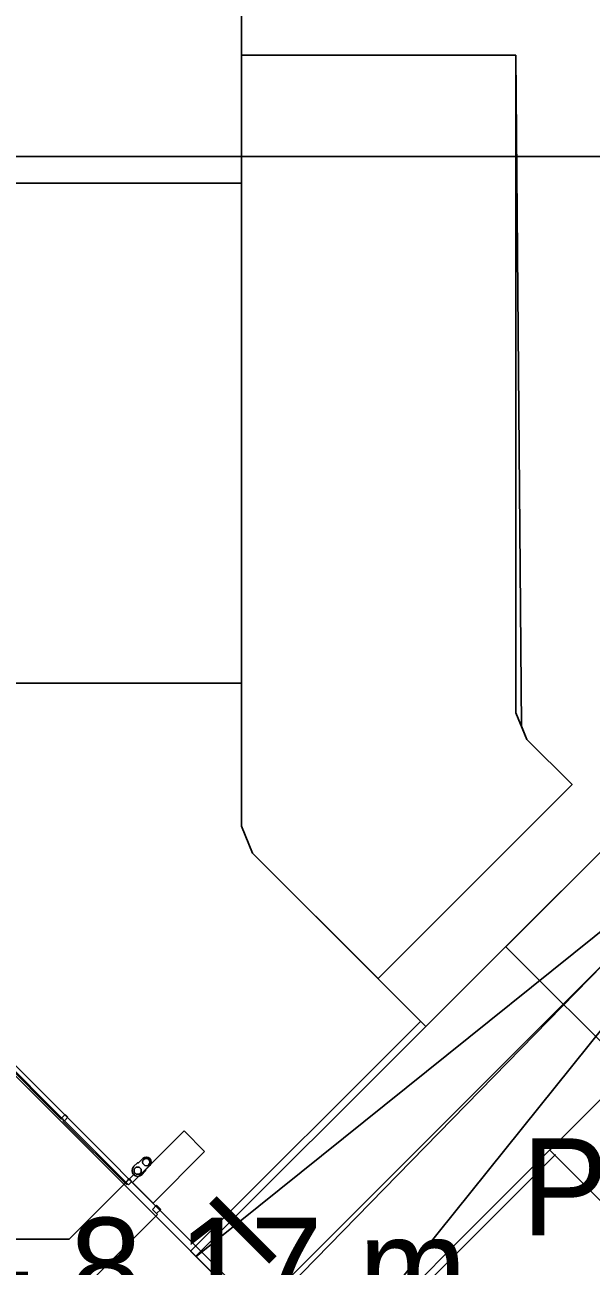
# Model space of a CAD drawing. Extents: x -264234 to -263604, y -1242346 to -1242049.
# Drawn here: x -263906.8 to -263895.14, y -1242233.35 to -1242207.77 of the extents above; entities that cross this region are included whole.
import ezdxf

# ---------------------------------------------------------------- set-up
doc = ezdxf.new("R2010")
doc.units = 0
for name, color, linetype in [('KFA_DAZDOVA_KANALIZACIA_retencna_nadrz_popis', 7, 'Continuous'), ('KFA_DAZDOVA_KANALIZACIA_vetva_I', 7, 'Continuous'), ('KFA_DAZDOVA_KANALIZACIA_vetva_I_popis', 7, 'Continuous'), ('KFA_SITUACIA_DSP', 7, 'Continuous')]:
    doc.layers.add(name, color=color, linetype=linetype)

msp = doc.modelspace()

# ---------------------------------------------------------------- linework, layer by layer
at = {"layer": 'KFA_DAZDOVA_KANALIZACIA_vetva_I'}
msp.add_lwpolyline([(-263814.907, -1242107.856), (-263815.198, -1242164.443), (-263815.189, -1242220.791), (-263852.152, -1242220.736), (-263888.701, -1242220.786), (-263906.731, -1242239.259)], dxfattribs=at)
at = {"layer": 'KFA_SITUACIA_DSP'}
for p, q in [((-263902.343, -1242208.394), (-263902.343, -1242224.282)), ((-263896.693, -1242208.394), (-263902.343, -1242208.394)), ((-263896.578, -1242222.219), (-263896.693, -1242208.394)), ((-263903.343, -1242211.032), (-263921.351, -1242211.032)), ((-263902.343, -1242211.032), (-263903.343, -1242211.032)), ((-263889.023, -1242221.253), (-263906.365, -1242238.596)), ((-263923.393, -1242221.332), (-263903.343, -1242221.332)), ((-263902.343, -1242221.332), (-263903.343, -1242221.332)), ((-263896.463, -1242222.496), (-263896.578, -1242222.219)), ((-263895.535, -1242223.424), (-263896.463, -1242222.496)), ((-263899.53, -1242227.419), (-263895.535, -1242223.424)), ((-263902.343, -1242224.282), (-263902.113, -1242224.837)), ((-263902.113, -1242224.837), (-263899.53, -1242227.419)), ((-263908.663, -1242227.55), (-263895.135, -1242241.078)), ((-263906.055, -1242230.32), (-263907.363, -1242229.012)), ((-263907.345, -1242228.994), (-263906.037, -1242230.303)), ((-263906.046, -1242230.294), (-263905.975, -1242230.223)), ((-263905.975, -1242230.223), (-263905.918, -1242230.28)), ((-263906.037, -1242230.303), (-263906.055, -1242230.32)), ((-263906.017, -1242230.322), (-263906.046, -1242230.294)), ((-263906.019, -1242230.356), (-263906.001, -1242230.338)), ((-263904.711, -1242231.664), (-263906.019, -1242230.356)), ((-263905.989, -1242230.351), (-263906.017, -1242230.322)), ((-263906.001, -1242230.338), (-263904.693, -1242231.647)), ((-263905.918, -1242230.28), (-263905.989, -1242230.351)), ((-263903.526, -1242230.561), (-263904.586, -1242231.622)), ((-263903.101, -1242230.985), (-263903.526, -1242230.561)), ((-263904.162, -1242232.046), (-263903.101, -1242230.985)), ((-263904.484, -1242231.218), (-263904.563, -1242231.296)), ((-263904.465, -1242231.218), (-263904.484, -1242231.218)), ((-263904.376, -1242231.13), (-263904.465, -1242231.218)), ((-263904.533, -1242231.432), (-263905.894, -1242232.793)), ((-263904.397, -1242231.462), (-263904.319, -1242231.383)), ((-263904.319, -1242231.383), (-263904.397, -1242231.462)), ((-263904.231, -1242231.275), (-263904.319, -1242231.364)), ((-263904.319, -1242231.364), (-263904.319, -1242231.383)), ((-263904.726, -1242231.613), (-263904.656, -1242231.543)), ((-263904.698, -1242231.642), (-263904.726, -1242231.613)), ((-263904.693, -1242231.647), (-263904.711, -1242231.664)), ((-263904.67, -1242231.67), (-263904.698, -1242231.642)), ((-263904.599, -1242231.599), (-263904.67, -1242231.67)), ((-263904.656, -1242231.543), (-263904.599, -1242231.599)), ((-263904.586, -1242231.622), (-263904.162, -1242232.046)), ((-263904.091, -1242232.093), (-263904.176, -1242232.178)), ((-263904.176, -1242232.178), (-263904.091, -1242232.263)), ((-263904.006, -1242232.178), (-263904.091, -1242232.093)), ((-263904.091, -1242232.263), (-263904.006, -1242232.178)), ((-263904.091, -1242232.263), (-263904.074, -1242232.281)), ((-263904.074, -1242232.281), (-263906.177, -1242234.384)), ((-263905.894, -1242232.793), (-263918.643, -1242232.793))]:
    msp.add_line(p, q, dxfattribs=at)
for points in [[(-263794.893, -1242227.382), (-263808.968, -1242241.457), (-263894.968, -1242241.457), (-263909.043, -1242227.382), (-263909.043, -1242196.333), (-263914.143, -1242196.333), (-263914.143, -1242132.433), (-263909.043, -1242132.433), (-263909.043, -1242101.382), (-263894.968, -1242087.307), (-263808.968, -1242087.307), (-263794.893, -1242101.382), (-263794.893, -1242227.382)], [(-263811.918, -1242108.434), (-263811.918, -1242220.33), (-263812.262, -1242220.675), (-263809.862, -1242221.669), (-263810.999, -1242222.806), (-263807.039, -1242226.765), (-263809.585, -1242229.311), (-263813.545, -1242225.351), (-263814.681, -1242226.488), (-263815.675, -1242224.088), (-263816.02, -1242224.432), (-263887.916, -1242224.432), (-263888.26, -1242224.088), (-263889.254, -1242226.488), (-263890.391, -1242225.351), (-263894.351, -1242229.311), (-263896.896, -1242226.765), (-263892.937, -1242222.806), (-263894.073, -1242221.669), (-263891.673, -1242220.675), (-263892.018, -1242220.33), (-263892.018, -1242181.432), (-263893.618, -1242181.432), (-263893.618, -1242147.332)], [(-263898.543, -1242228.407), (-263902.112, -1242224.837), (-263902.343, -1242224.282), (-263902.343, -1242203.332), (-263909.043, -1242203.332)], [(-263891.673, -1242220.675), (-263894.073, -1242221.669), (-263892.937, -1242222.806), (-263898.544, -1242228.407)], [(-263895.995, -1242230.956), (-263890.391, -1242225.352), (-263889.254, -1242226.488), (-263888.26, -1242224.088), (-263891.673, -1242220.675)], [(-263903.277, -1242233.148), (-263900.731, -1242235.694), (-263890.333, -1242222.748), (-263903.277, -1242233.148)], [(-263898.65, -1242228.301), (-263903.39, -1242233.035), (-263900.629, -1242235.796), (-263895.875, -1242231.049)], [(-263898.544, -1242228.407), (-263903.281, -1242233.144), (-263900.731, -1242235.694), (-263895.982, -1242230.943)], [(-263807.942, -1242230.956), (-263811.512, -1242234.526), (-263812.068, -1242234.757), (-263891.868, -1242234.757), (-263892.424, -1242234.526), (-263895.994, -1242230.956)]]:
    msp.add_lwpolyline(points, dxfattribs=at)
for points in [[(-263893.618, -1242118.282), (-263916.093, -1242118.282), (-263916.093, -1242175.482), (-263914.293, -1242175.482), (-263914.293, -1242210.482), (-263893.618, -1242210.482), (-263893.618, -1242166.382), (-263900.043, -1242166.382), (-263900.043, -1242162.382), (-263893.618, -1242162.382)], [(-263896.693, -1242208.394), (-263902.343, -1242208.394), (-263902.343, -1242224.282), (-263902.113, -1242224.837), (-263899.53, -1242227.419), (-263895.535, -1242223.424), (-263896.463, -1242222.496), (-263896.693, -1242221.942)]]:
    msp.add_lwpolyline(points, close=True, dxfattribs=at)
for centre in [(-263904.303, -1242231.202), (-263904.48, -1242231.379)]:
    msp.add_circle(centre, 0.075, dxfattribs=at)
for centre, radius, start, end in [((-263904.303, -1242231.202), 0.103, 315, 135), ((-263904.48, -1242231.379), 0.117, 135, 315)]:
    msp.add_arc(centre, radius, start, end, dxfattribs=at)

# ---------------------------------------------------------------- texts
at = {"layer": 'KFA_DAZDOVA_KANALIZACIA_retencna_nadrz_popis'}
msp.add_text('NRN, PVC DN600 - 8,17 m', height=2, dxfattribs=at).set_placement((-263930.102, -1242234.349))
at = {"layer": 'KFA_DAZDOVA_KANALIZACIA_vetva_I_popis'}
msp.add_text('PVC DN400 - 25,81 m', height=2, dxfattribs=at).set_placement((-263896.573, -1242232.714))
at = {"layer": 'KFA_SITUACIA_DSP'}
msp.add_text('I', height=1.75, rotation=45.0119, dxfattribs=at).set_placement((-263901.924, -1242233.448))

doc.saveas('drawing.dxf')
